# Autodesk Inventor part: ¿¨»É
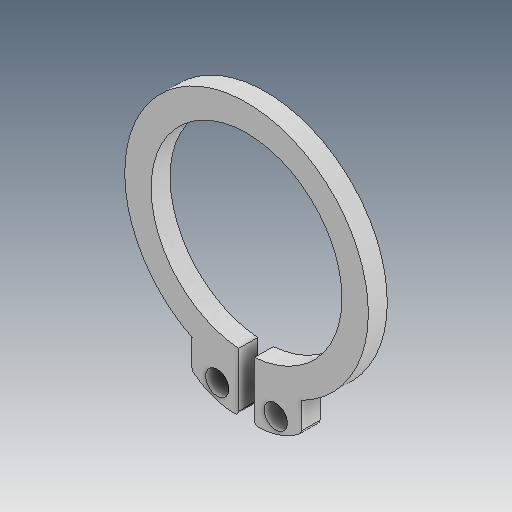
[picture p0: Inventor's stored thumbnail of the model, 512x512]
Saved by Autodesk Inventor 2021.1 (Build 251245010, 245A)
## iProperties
Created: 2019-05
Part Number: ¿¨»É
Material: Ogólny
Document SubType Name: Modeling
Designer: user
Density: 1 g/cm^3
Appearance: Domyślna
Author: user
Revision Number: ÈÎºÎ
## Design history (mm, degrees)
feature "ÊäÈë1"
node "Bryła1"
